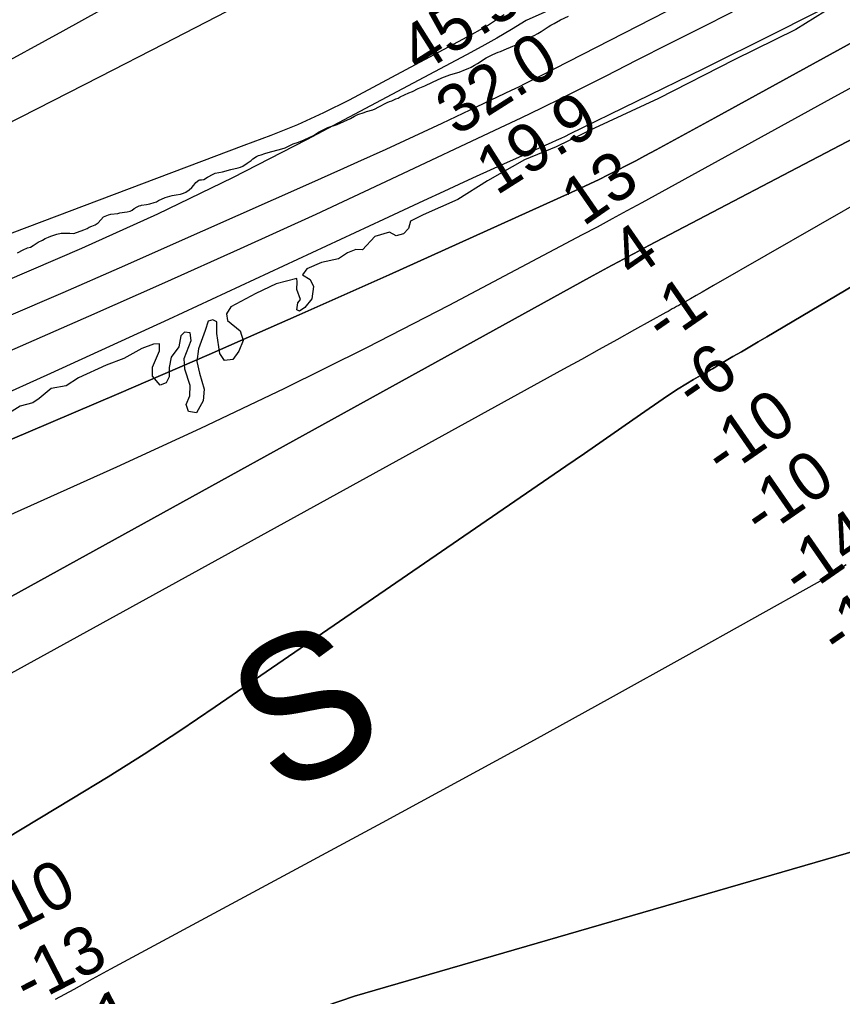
# Model space of a CAD drawing. Extents: x 3177385 to 3215275, y 903885 to 929304.
# Drawn here: x 3199851 to 3201001, y 915578 to 916943 of the extents above; entities that cross this region are included whole.
import ezdxf

# ---------------------------------------------------------------- set-up
doc = ezdxf.new("R2010")
doc.units = 0
for name, color, linetype in [('V-RIVR-EDGE', 7, 'Continuous'), ('V-RIVR-IDEN', 7, 'Continuous'), ('V-RIVR-RANG', 7, 'Continuous'), ('V-SITE-VEGE', 7, 'Continuous'), ('V-TOPO-DPTH', 7, 'Continuous'), ('V-TOPO-MAJR', 7, 'Continuous'), ('V-TOPO-MINR', 7, 'Continuous'), ('V-TOPO-WATR', 7, 'Continuous')]:
    doc.layers.add(name, color=color, linetype=linetype)

msp = doc.modelspace()

# ---------------------------------------------------------------- linework, layer by layer
at = {"layer": 'V-RIVR-EDGE'}
for points in [[(3201003.5, 916971.1), (3200935.9, 916928.7), (3200849.9, 916886.5), (3200744, 916832.7), (3200654.8, 916790.9), (3200601.1, 916765.1), (3200556.7, 916746.8), (3200504.9, 916717.3), (3200463.8, 916691.6), (3200415.2, 916670), (3200397.7, 916661.3), (3200394.9, 916651.1), (3200387.9, 916643.3), (3200377.7, 916640.5), (3200368.1, 916645.6), (3200347.7, 916639.7), (3200330.6, 916621.2), (3200321.3, 916621.7), (3200309.3, 916617.1), (3200296.8, 916608.4), (3200273.3, 916603.4), (3200252.5, 916594.6), (3200246.4, 916586.3), (3200257.5, 916579.8), (3200262.1, 916570.1), (3200259.7, 916552.6), (3200250, 916540.6), (3200242.6, 916535.5), (3200238.5, 916537.4), (3200240.3, 916547.1), (3200243.6, 916551.7), (3200238.5, 916565.6), (3200239, 916576.2), (3200238.6, 916581.3), (3200209.9, 916573.5), (3200181.2, 916560.2), (3200146.6, 916541.3), (3200140.5, 916531.6), (3200141.9, 916522.4), (3200159.4, 916508), (3200163.5, 916494.6), (3200157.5, 916479.4), (3200149.1, 916467.9), (3200137.6, 916466.5), (3200131.2, 916476.2), (3200127.1, 916504.4), (3200127.1, 916520.6), (3200121.1, 916523.4), (3200114.6, 916521.5), (3200110.4, 916508.6), (3200101.1, 916482.8), (3200098.8, 916465.2), (3200102.9, 916448.6), (3200109.3, 916426.4), (3200107.9, 916410.2), (3200098.6, 916393.6), (3200087.1, 916395.1), (3200083.9, 916405.2), (3200089.4, 916417.2), (3200089.5, 916431.5)], [(3200089.5, 916431.5), (3200082.1, 916454.2), (3200081.3, 916469.4), (3200091, 916494.4), (3200089.7, 916505.4), (3200081.8, 916505.9), (3200076.7, 916500.9), (3200073.9, 916485.6), (3200063.2, 916471.3), (3200060.4, 916456.6), (3200060.4, 916443.6), (3200056.2, 916435.3), (3200047.9, 916432.1), (3200036.9, 916444.6), (3200036.9, 916457.1), (3200046.6, 916480.1), (3200046.7, 916489.8), (3200038.3, 916489.4), (3200022.2, 916483.4), (3199997.2, 916469.2), (3199972.2, 916460), (3199933.8, 916442.1), (3199916.3, 916431), (3199895.5, 916427.4), (3199878.8, 916413.6), (3199870, 916407.6), (3199852, 916402.6), (3199837.2, 916393.4)]]:
    msp.add_lwpolyline(points, dxfattribs=at)
at = {"layer": 'V-SITE-VEGE'}
for points in [[(3200380.1, 916833), (3200382.9, 916834.9), (3200395, 916840.3), (3200400.4, 916842.5), (3200408, 916846.3), (3200417.3, 916850.4), (3200428.4, 916855.2), (3200441.4, 916861.6), (3200452.5, 916865.7), (3200460.2, 916867.9), (3200465.6, 916869.2), (3200474.2, 916873), (3200478, 916874.3), (3200482.1, 916876.2), (3200486.9, 916879.1), (3200491, 916881.6), (3200503.1, 916889.5), (3200512.6, 916894), (3200520.2, 916897.2), (3200523.1, 916898.1), (3200528.2, 916900.7), (3200540.3, 916905.4), (3200547.6, 916908.6), (3200553.6, 916912.1), (3200557.8, 916914), (3200562.8, 916917.2), (3200570.5, 916920.7), (3200575.2, 916923.2), (3200580.3, 916926.1), (3200589.9, 916932.8), (3200593.4, 916935), (3200598.1, 916937.2), (3200607.3, 916942.3), (3200618.1, 916947.4)], [(3199848.3, 916616.8), (3199856.5, 916621.2), (3199862.6, 916623.7), (3199866.4, 916625), (3199870.5, 916627.2), (3199877.5, 916631.7), (3199883.2, 916634.6), (3199887, 916636.8), (3199891.8, 916639), (3199895, 916640.3), (3199903.3, 916643.1), (3199909.6, 916644.4), (3199921.7, 916644.4), (3199927.1, 916644.1), (3199941.1, 916648.9), (3199945.8, 916651.1), (3199948.7, 916652.7), (3199952.5, 916654.3), (3199957, 916655.9), (3199961.1, 916658.7), (3199968.7, 916667.3), (3199975.4, 916669.9), (3199978.9, 916670.8), (3199988.4, 916671.8), (3199991.6, 916672.7), (3199994.8, 916673.3), (3199998, 916673.7), (3200001.5, 916674.3), (3200005.6, 916675.3), (3200008.5, 916676.5), (3200011.6, 916678.8), (3200015.5, 916681), (3200018.6, 916682.6), (3200020.5, 916683.2), (3200021.8, 916683.5), (3200028.8, 916684.5), (3200033.3, 916685.4), (3200039.3, 916687), (3200042.5, 916688.3), (3200045.3, 916689.9), (3200054.9, 916694), (3200064.7, 916696.9), (3200070.1, 916698.1), (3200076.2, 916699.1), (3200080.3, 916700.1), (3200083.5, 916701.6), (3200088.3, 916704.8), (3200092.1, 916708.3), (3200094.6, 916711.5), (3200097.8, 916715), (3200101.9, 916718.2), (3200103.2, 916718.8), (3200105.4, 916718.8), (3200108.6, 916719.4), (3200113.7, 916722.6), (3200121.6, 916726.8), (3200124.5, 916728), (3200135, 916730.3), (3200146.7, 916733.4), (3200156.9, 916735.7), (3200159.8, 916736.6), (3200163.3, 916738.2), (3200169.3, 916742), (3200174.7, 916745.8), (3200177.3, 916748.1), (3200182.3, 916751.6), (3200185.2, 916752.8), (3200189, 916753.8), (3200193.8, 916755.7), (3200201.7, 916758.2), (3200214.5, 916761.1), (3200222.4, 916763.6), (3200233.8, 916769), (3200240.8, 916771.3), (3200249.1, 916774.8), (3200261.8, 916780.8), (3200266.3, 916783.7), (3200269.1, 916785.3), (3200282.2, 916791.9), (3200294.9, 916796.1), (3200313.9, 916804.7), (3200319.4, 916807.8), (3200324.1, 916810.1), (3200332.7, 916812.9), (3200335.9, 916814.2), (3200344.8, 916816.7), (3200348.3, 916818.3), (3200352.4, 916820.6), (3200365.1, 916826.9), (3200368.3, 916828.2), (3200371.5, 916829.1), (3200377.2, 916832), (3200380.1, 916833)]]:
    msp.add_lwpolyline(points, dxfattribs=at)
at = {"layer": 'V-TOPO-DPTH'}
for points in [[(3201159.3, 916990.6), (3200822.9, 916805.5), (3200802.4, 916794.3), (3200781.9, 916783.1), (3200761.3, 916771.9), (3200740.7, 916760.8), (3200724.9, 916752.3), (3200712.2, 916745.5), (3200699.4, 916738.8), (3200686.6, 916732.3), (3200673.8, 916725.8), (3200660.9, 916719.4), (3200647.9, 916713.2), (3200634.9, 916707.1), (3200621.8, 916701.1), (3200367.7, 916586.4), (3200242.1, 916530.3), (3200116.2, 916474.8), (3199990, 916420.3), (3199863.5, 916366.3), (3199615.8, 916261.7)], [(3199615.8, 916261.7), (3199863.5, 916366.3), (3199990, 916420.3), (3200116.2, 916474.8), (3200242.1, 916530.3), (3200367.7, 916586.4), (3200621.8, 916701.1), (3200634.9, 916707.1), (3200647.9, 916713.2), (3200660.9, 916719.4), (3200673.8, 916725.8), (3200686.6, 916732.3), (3200699.4, 916738.8), (3200712.2, 916745.5), (3200724.9, 916752.3), (3200740.7, 916760.8), (3200761.3, 916771.9), (3200781.9, 916783.1), (3200802.4, 916794.3), (3200822.9, 916805.5), (3201159.3, 916990.6)], [(3200846.9, 916953.3), (3200802.5, 916930.8), (3200758.2, 916908.3), (3200713.8, 916885.9), (3200669.4, 916863.4), (3200637.7, 916847.4), (3200609.1, 916833.1), (3200580.4, 916819), (3200551.7, 916805.1), (3200522.8, 916791.4), (3200370.5, 916719.7), (3200265.3, 916670.7), (3200159.7, 916622.3), (3200053.8, 916574.8), (3199947.6, 916527.8), (3199729.7, 916432.7)], [(3199832.4, 915798.8), (3199924.4, 915854), (3199975.1, 915885.1), (3200025.5, 915916.8), (3200075.2, 915949.4), (3200124.6, 915982.6), (3200614.6, 916318.9), (3200640.8, 916336.8), (3200666.9, 916354.9), (3200693, 916373), (3200719, 916391.1), (3200750.7, 916413.1), (3200761, 916420.1), (3200771.4, 916426.9), (3200782, 916433.4), (3200792.7, 916439.8), (3200809.4, 916449.3), (3200811.9, 916450.7), (3200814.3, 916452.2), (3200816.8, 916453.6), (3200819.3, 916455), (3200821.8, 916456.5), (3200824.3, 916457.9), (3200826.8, 916459.4), (3200829.2, 916460.8), (3200847.9, 916471.9), (3200859.8, 916478.8), (3200871.6, 916485.8), (3200883.4, 916492.8), (3200895.2, 916499.8), (3201503, 916859.5)], [(3199832.4, 915798.8), (3199924.4, 915854), (3199975.1, 915885.1), (3200025.5, 915916.8), (3200075.2, 915949.4), (3200124.6, 915982.6), (3200614.6, 916318.9), (3200640.8, 916336.8), (3200666.9, 916354.9), (3200693, 916373), (3200719, 916391.1), (3200750.7, 916413.1), (3200761, 916420.1), (3200771.4, 916426.9), (3200782, 916433.4), (3200792.7, 916439.8), (3200809.4, 916449.3), (3200811.9, 916450.7), (3200814.3, 916452.2), (3200816.8, 916453.6), (3200819.3, 916455), (3200821.8, 916456.5), (3200824.3, 916457.9), (3200826.8, 916459.4), (3200829.2, 916460.8), (3200847.9, 916471.9), (3200859.8, 916478.8), (3200871.6, 916485.8), (3200883.4, 916492.8), (3200895.2, 916499.8), (3201503, 916859.5)], [(3201016.8, 916777.3), (3200730.7, 916627.2), (3200720.2, 916621.7), (3200709.8, 916616.1), (3200699.3, 916610.6), (3200688.9, 916605), (3200678.5, 916599.4), (3200668.1, 916593.8), (3200657.7, 916588.2), (3200647.4, 916582.5), (3199705.1, 916062.9), (3199697, 916058.6), (3199689, 916054.3), (3199680.8, 916050.2), (3199672.6, 916046.1), (3199542.8, 915982.9), (3199469.4, 915947.8), (3199395.7, 915913.4), (3199321.6, 915879.9), (3199247.1, 915847.2), (3198765.9, 915639.7)], [(3198765.9, 915639.7), (3199247.1, 915847.2), (3199321.6, 915879.9), (3199395.7, 915913.4), (3199469.4, 915947.8), (3199542.8, 915982.9), (3199672.6, 916046.1), (3199680.8, 916050.2), (3199689, 916054.3), (3199697, 916058.6), (3199705.1, 916062.9), (3200647.4, 916582.5), (3200657.7, 916588.2), (3200668.1, 916593.8), (3200678.5, 916599.4), (3200688.9, 916605), (3200699.3, 916610.6), (3200709.8, 916616.1), (3200720.2, 916621.7), (3200730.7, 916627.2), (3201016.8, 916777.3)], [(3201006, 916180.9), (3200992.9, 916172.2), (3200979.5, 916164), (3200965.9, 916156.1), (3200782.1, 916053.5), (3200676.3, 915994.7), (3200570.4, 915936.3), (3200464.1, 915878.3), (3200357.8, 915820.7), (3199978.5, 915616.3), (3199952.7, 915602.3), (3199926.9, 915588.1), (3199901.2, 915573.7)], [(3201006, 916180.9), (3200992.9, 916172.2), (3200979.5, 916164), (3200965.9, 916156.1), (3200782.1, 916053.5), (3200676.3, 915994.7), (3200570.4, 915936.3), (3200464.1, 915878.3), (3200357.8, 915820.7), (3199978.5, 915616.3), (3199952.7, 915602.3), (3199926.9, 915588.1), (3199901.2, 915573.7)], [(3200136.3, 915516.2), (3200319.1, 915578.5), (3201081.8, 915799.7)], [(3201081.8, 915799.7), (3200319.1, 915578.5), (3200136.3, 915516.2)]]:
    msp.add_lwpolyline(points, dxfattribs=at)
at = {"layer": 'V-TOPO-MAJR'}
msp.add_lwpolyline([(3200528.5, 916949.6), (3200517.5, 916942.2), (3200506.3, 916935.1), (3200494.9, 916928.3), (3200483.3, 916921.9), (3200312, 916830.4), (3200276, 916812.4), (3200239.6, 916795.6), (3200202.4, 916780.6), (3200164.6, 916766.8), (3199477.9, 916507.3)], dxfattribs=at)
at = {"layer": 'V-TOPO-MINR'}
for points in [[(3198680.1, 916423.5), (3199341, 916632.8), (3199362.4, 916642.6), (3199383.8, 916652.5), (3199404.9, 916662.8), (3199426, 916673.3), (3199596.5, 916759.8), (3199702.4, 916814.4), (3199807.8, 916870.1), (3199912.3, 916927.2), (3200016.4, 916985.2), (3200317.9, 917156.3), (3200335.2, 917166.3), (3200352.3, 917176.6), (3200369.3, 917187.1), (3200386.1, 917197.8), (3200958.3, 917570.4), (3201001.6, 917598.9), (3201044.9, 917627.6), (3201087.9, 917656.7), (3201130.7, 917686)], [(3201091.4, 917179.4), (3200559.2, 916941.5), (3200538.6, 916929.1), (3200517.9, 916917), (3200497, 916905.2), (3200475.9, 916893.7), (3200252.4, 916775), (3200148.7, 916721.8), (3200044, 916670.8), (3199937.9, 916622.9), (3199830.8, 916577.1)], [(3201004.8, 916973.5), (3200906, 916923.3), (3200806.7, 916874), (3200619.8, 916782.6), (3200613.6, 916779.6), (3200607.4, 916776.7), (3200601.1, 916773.8), (3200594.9, 916771), (3200567.9, 916759.1), (3200548.2, 916750.2), (3200528.5, 916741.4), (3200508.8, 916732.5), (3200489.2, 916723.5), (3200472.1, 916715.6), (3200444, 916702.7), (3200415.8, 916689.7), (3200387.7, 916676.7), (3200359.6, 916663.6), (3200059.3, 916524), (3199976.9, 916486), (3199894.4, 916448.4), (3199811.7, 916411.3)], [(3200141, 916953.9), (3200052.3, 916908.2), (3199963.6, 916862.7), (3199874.8, 916817.4), (3199437.9, 916595.1), (3199428, 916590.2), (3199418, 916585.4), (3199407.9, 916580.7), (3199397.8, 916576.2), (3199314.3, 916539.7), (3199262.3, 916517.2), (3199210.2, 916494.8), (3199158, 916472.6), (3199105.8, 916450.5), (3198421.9, 916163.7)], [(3200846.9, 916953.3), (3200802.5, 916930.8), (3200758.2, 916908.3), (3200713.8, 916885.9), (3200669.4, 916863.4), (3200637.7, 916847.4), (3200609.1, 916833.1), (3200580.4, 916819), (3200551.7, 916805.1), (3200522.8, 916791.4), (3200370.5, 916719.7), (3200265.3, 916670.7), (3200159.7, 916622.3), (3200053.8, 916574.8), (3199947.6, 916527.8), (3199729.7, 916432.7)], [(3200754.1, 916953.5), (3200578.7, 916863.7), (3200568.6, 916858.5), (3200558.4, 916853.5), (3200548.2, 916848.4), (3200538, 916843.5), (3200480.5, 916816), (3200441.4, 916797.5), (3200402.2, 916779.2), (3200362.9, 916761.2), (3200323.5, 916743.4), (3200304.1, 916734.7), (3200254.9, 916712.7), (3200205.7, 916690.8), (3200156.4, 916668.9), (3200107.1, 916647.1), (3199990.3, 916595.6), (3199911.6, 916561.1), (3199832.8, 916526.9)], [(3201073, 916880.2), (3200994.2, 916837), (3200915.4, 916793.8), (3200836.7, 916750.6), (3200720.7, 916686.8), (3200699.9, 916675.5), (3200679.1, 916664.2), (3200658.3, 916653), (3200637.4, 916642), (3200450.9, 916543.5), (3200336.1, 916484.4), (3200220.7, 916426.8), (3200104.1, 916371.4), (3199986.9, 916317.4), (3199640.3, 916162)], [(3201332.8, 916864.5), (3200821, 916571.4), (3200812.9, 916566.7), (3200804.8, 916562.1), (3200796.6, 916557.4), (3200788.5, 916552.8), (3200778.1, 916546.8), (3200775.1, 916545.2), (3200772.2, 916543.5), (3200769.2, 916541.8), (3200766.3, 916540.1), (3200763.3, 916538.5), (3200760.4, 916536.8), (3200757.4, 916535.2), (3200754.4, 916533.5), (3200710.7, 916509.2), (3200685.9, 916495.4), (3200661, 916481.7), (3200636.2, 916467.9), (3200611.3, 916454.2), (3199742.1, 915976.4)], [(3201503, 916859.5), (3200895.2, 916499.8), (3200883.4, 916492.8), (3200871.6, 916485.8), (3200859.8, 916478.8), (3200847.9, 916471.9), (3200829.2, 916460.8), (3200826.8, 916459.4), (3200824.3, 916457.9), (3200821.8, 916456.5), (3200819.3, 916455), (3200816.8, 916453.6), (3200814.3, 916452.2), (3200811.9, 916450.7), (3200809.4, 916449.3), (3200792.7, 916439.8), (3200782, 916433.4), (3200771.4, 916426.9), (3200761, 916420.1), (3200750.7, 916413.1), (3200719, 916391.1), (3200693, 916373), (3200666.9, 916354.9), (3200640.8, 916336.8), (3200614.6, 916318.9), (3200124.6, 915982.6), (3200075.2, 915949.4), (3200025.5, 915916.8), (3199975.1, 915885.1), (3199924.4, 915854), (3199832.4, 915798.8)], [(3201016.8, 916777.3), (3200730.7, 916627.2), (3200720.2, 916621.7), (3200709.8, 916616.1), (3200699.3, 916610.6), (3200688.9, 916605), (3200678.5, 916599.4), (3200668.1, 916593.8), (3200657.7, 916588.2), (3200647.4, 916582.5), (3199705.1, 916062.9), (3199697, 916058.6), (3199689, 916054.3), (3199680.8, 916050.2), (3199672.6, 916046.1), (3199542.8, 915982.9), (3199469.4, 915947.8), (3199395.7, 915913.4), (3199321.6, 915879.9), (3199247.1, 915847.2), (3198765.9, 915639.7)], [(3201006, 916180.9), (3200992.9, 916172.2), (3200979.5, 916164), (3200965.9, 916156.1), (3200782.1, 916053.5), (3200676.3, 915994.7), (3200570.4, 915936.3), (3200464.1, 915878.3), (3200357.8, 915820.7), (3199978.5, 915616.3), (3199952.7, 915602.3), (3199926.9, 915588.1), (3199901.2, 915573.7)], [(3201081.8, 915799.7), (3200319.1, 915578.5), (3200136.3, 915516.2)]]:
    msp.add_lwpolyline(points, dxfattribs=at)
at = {"layer": 'V-TOPO-WATR'}
msp.add_lwpolyline([(3201159.3, 916990.6), (3200822.9, 916805.5), (3200802.4, 916794.3), (3200781.9, 916783.1), (3200761.3, 916771.9), (3200740.7, 916760.8), (3200724.9, 916752.3), (3200712.2, 916745.5), (3200699.4, 916738.8), (3200686.6, 916732.3), (3200673.8, 916725.8), (3200660.9, 916719.4), (3200647.9, 916713.2), (3200634.9, 916707.1), (3200621.8, 916701.1), (3200367.7, 916586.4), (3200242.1, 916530.3), (3200116.2, 916474.8), (3199990, 916420.3), (3199863.5, 916366.3), (3199615.8, 916261.7)], dxfattribs=at)

# ---------------------------------------------------------------- texts
at = {"layer": 'V-RIVR-IDEN'}
msp.add_text('S', height=200, rotation=25.1256, dxfattribs=at).set_placement((3200210.2, 915855.7))
at = {"layer": 'V-RIVR-RANG'}
for s, rotation, p in [('45.5', 32.3883, (3200410.2, 916864.9)), ('32.0', 32.3883, (3200461.5, 916779.1)), ('19.9', 32.3883, (3200517.5, 916696.2)), ('13', 34.6739, (3200638.8, 916652.8)), ('4', 34.6739, (3200708, 916579.1)), ('-1', 34.6739, (3200751.3, 916487.6)), ('-6', 34.6739, (3200793.6, 916395.3)), ('-10', 34.6739, (3200834.2, 916301.9)), ('-10', 34.6739, (3200887.9, 916217.6)), ('-14', 34.6739, (3200942.6, 916133.9)), ('-17', 34.6739, (3200996.1, 916049.4)), ('-10', 27.1739, (3199819.7, 915654.4)), ('-13', 27.1739, (3199863, 915564.2)), ('-21', 27.1739, (3199908.7, 915475.3))]:
    msp.add_text(s, height=67, rotation=rotation, dxfattribs=at).set_placement(p)

doc.saveas('drawing.dxf')
